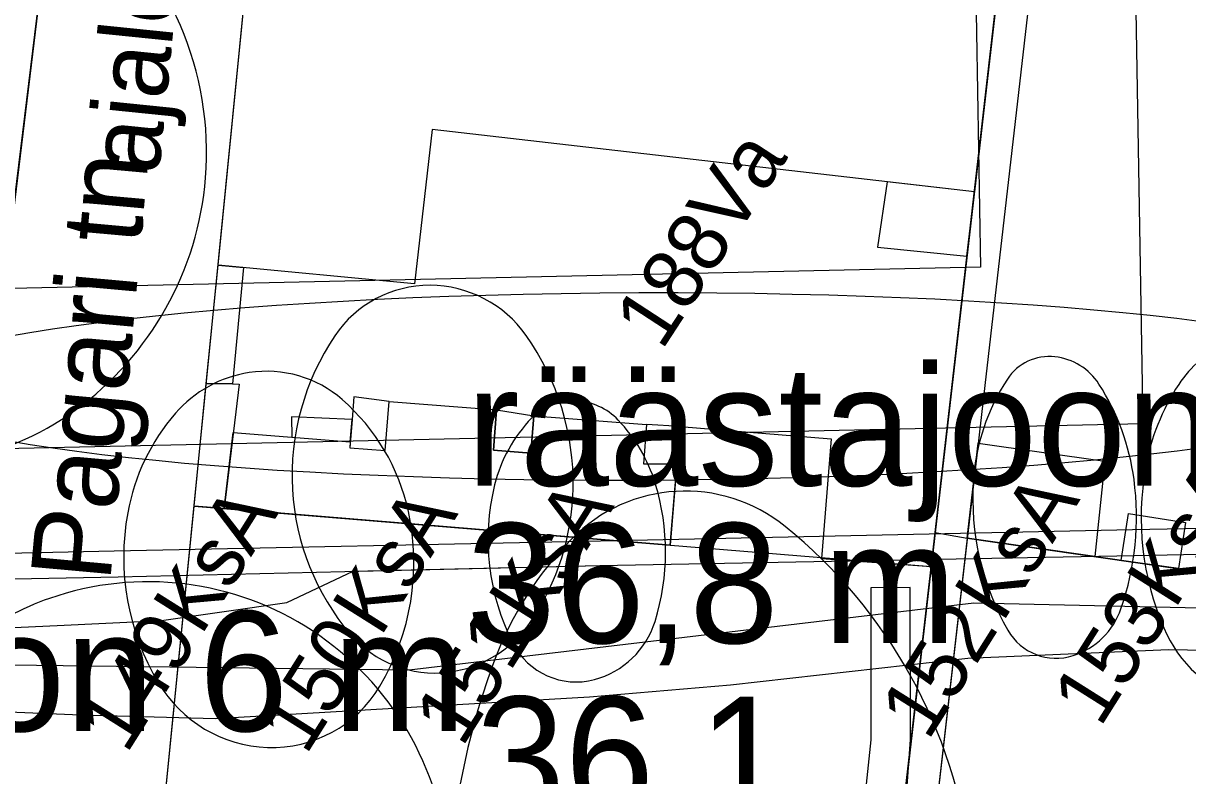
# Model space of a CAD drawing. Extents: x 738423 to 738903, y 6589762 to 6590172.
# Drawn here: x 738632.2 to 738661.32, y 6589875.49 to 6589894.31 of the extents above; entities that cross this region are included whole.
import ezdxf

# ---------------------------------------------------------------- set-up
doc = ezdxf.new("R2010")
doc.units = 0
for name, color, linetype in [('_1927_hoonestus', 7, 'Continuous'), ('_1927_katuse_kalded', 7, 'Continuous'), ('_1927_koordin_punktid_nr', 7, 'Continuous'), ('_1927_krundi_piir', 7, 'Continuous'), ('_a_ajalooline_maapind', 7, 'Continuous'), ('_a_olol_maapind', 7, 'Continuous'), ('_arheol_Raamatukogu_tranžee', 7, 'Continuous'), ('a_dendro_II_Vkl_puu', 7, 'Continuous'), ('a_dendro_III_vk_puu', 7, 'Continuous'), ('a_dendro_puu_nr', 7, 'Continuous'), ('a_dendro_V_vk_puu', 7, 'Continuous'), ('Default', 7, 'Continuous'), ('v_dp_jalak_liikumine', 7, 'Continuous'), ('v_olol_kitsendus_tehnov', 7, 'Continuous'), ('v_olol_kivimuur', 7, 'Continuous'), ('v_olol_transp_jjt_jalg', 7, 'Continuous'), ('v_vormistus_tekst', 7, 'Continuous')]:
    doc.layers.add(name, color=color, linetype=linetype)

# ---------------------------------------------------------------- blocks, each defined once
blk = doc.blocks.new('_U577')
at = {"layer": 'Default'}
for centre, radius, start, end in [((0.0003539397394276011, -0.0024772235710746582), 0.01753301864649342, 95.06339460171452, 143.64928581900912), ((0.0003509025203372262, -0.0024429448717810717), 0.017498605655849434, 47.6139328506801, 95.06339460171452), ((0.006587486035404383, 0.004390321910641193), 0.008247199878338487, 335.85757945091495, 47.613932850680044), ((-0.007106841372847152, 0.0030134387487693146), 0.008269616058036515, 143.6492858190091, 217.25092224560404), ((0.00326511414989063, 0.0058794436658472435), 0.011888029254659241, 301.16151048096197, 335.85757945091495), ((-0.004085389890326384, 0.00531108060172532), 0.012065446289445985, 217.2509222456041, 249.96613917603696), ((-0.0012283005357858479, 0.013310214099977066), 0.02057175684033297, 274.9595126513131, 301.16151048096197), ((-0.0012168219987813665, 0.01317793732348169), 0.020438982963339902, 249.96613917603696, 274.9595126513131)]:
    blk.add_arc(centre, radius, start, end, dxfattribs=at)
blk = doc.blocks.new('_U581')
at = {"layer": 'Default'}
for centre, radius, start, end in [((-0.0003533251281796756, -0.035605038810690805), 0.04161816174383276, 90.22599422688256, 110.7235512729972), ((-0.0003746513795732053, -0.03019827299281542), 0.0362113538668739, 73.7512051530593, 90.22599422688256), ((0.004875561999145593, -0.012184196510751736), 0.01744778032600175, 49.92756766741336, 73.75120515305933), ((-0.007667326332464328, -0.016273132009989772), 0.02094892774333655, 110.7235512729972, 139.77080809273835), ((0.010993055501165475, -0.004912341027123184), 0.007944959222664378, 325.34619088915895, 49.92756766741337), ((-0.017226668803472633, -0.008186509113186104), 0.00842796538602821, 139.77080809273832, 235.64822831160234), ((-0.003462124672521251, 0.005079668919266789), 0.025517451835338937, 281.2397286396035, 325.3461908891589), ((-0.004520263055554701, 0.010404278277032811), 0.030946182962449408, 235.64822831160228, 281.2397286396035)]:
    blk.add_arc(centre, radius, start, end, dxfattribs=at)
blk = doc.blocks.new('_U582')
at = {"layer": 'Default'}
for centre, radius, start, end in [((-0.0007850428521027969, -0.005273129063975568), 0.015274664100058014, 90.12335565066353, 129.24551704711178), ((-0.000785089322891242, -0.005251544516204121), 0.015253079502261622, 56.96948488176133, 90.12335565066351), ((-0.0006696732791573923, -0.005074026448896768), 0.015041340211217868, 23.57628563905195, 56.969484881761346), ((-0.0009275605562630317, -0.005098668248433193), 0.0150493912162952, 129.24551704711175, 168.67143080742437), ((-0.0005917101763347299, -0.0050400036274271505), 0.014956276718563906, 330.9480012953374, 23.57628563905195), ((-0.0010119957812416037, -0.005081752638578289), 0.014963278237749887, 168.6714308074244, 224.00059475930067), ((-0.0008142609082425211, -0.004916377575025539), 0.015210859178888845, 278.7954697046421, 330.9480012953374), ((-0.0008177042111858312, -0.0048941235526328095), 0.01523337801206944, 224.00059475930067, 278.7954697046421)]:
    blk.add_arc(centre, radius, start, end, dxfattribs=at)
blk = doc.blocks.new('_U599')
at = {"layer": 'Default'}
for centre, radius, start, end in [((-0.0018151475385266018, -0.00620660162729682), 0.012288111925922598, 83.93806732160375, 125.09681026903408), ((-0.0016240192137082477, -0.0044068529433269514), 0.010478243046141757, 53.38644184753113, 83.93806732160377), ((-0.005065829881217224, -0.0015808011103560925), 0.006634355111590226, 125.09681026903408, 182.2562888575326), ((0.0009823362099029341, -0.0008991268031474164), 0.006108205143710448, 13.013863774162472, 53.386441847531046), ((0.0013255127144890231, -0.0008198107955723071), 0.005755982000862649, 323.219360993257, 13.013863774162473), ((-0.005418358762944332, -0.0015946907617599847), 0.006281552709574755, 182.25628885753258, 243.4810712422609), ((-0.0023411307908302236, 0.0019212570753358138), 0.010333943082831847, 286.5947773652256, 323.21936099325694), ((-0.002835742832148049, 0.0035809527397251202), 0.012065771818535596, 243.48107124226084, 286.5947773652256)]:
    blk.add_arc(centre, radius, start, end, dxfattribs=at)
blk = doc.blocks.new('_U600')
at = {"layer": 'Default'}
for centre, radius, start, end in [((0.0009964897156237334, -0.005254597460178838), 0.012167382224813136, 97.43302717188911, 134.77200971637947), ((0.0010458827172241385, -0.005633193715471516), 0.012549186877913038, 60.34283130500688, 97.43302717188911), ((0.004430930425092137, 0.0003117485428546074), 0.005708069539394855, 4.068377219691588, 60.342831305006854), ((-0.00366957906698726, -0.0005512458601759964), 0.005542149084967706, 134.77200971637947, 191.4000956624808), ((0.004221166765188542, 0.00029682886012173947), 0.005918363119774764, 309.53088612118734, 4.068377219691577), ((-0.0033526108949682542, -0.00048733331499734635), 0.005865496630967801, 191.4000956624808, 240.15642242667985), ((-0.0001874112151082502, 0.005638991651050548), 0.012844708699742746, 273.2918787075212, 309.53088612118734), ((-0.00015555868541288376, 0.005085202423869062), 0.01229000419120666, 240.1564224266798, 273.2918787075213)]:
    blk.add_arc(centre, radius, start, end, dxfattribs=at)
blk = doc.blocks.new('_U601')
at = {"layer": 'Default'}
for centre, radius, start, end in [((-0.0022618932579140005, -0.007197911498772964), 0.011375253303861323, 80.41226363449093, 121.45839542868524), ((-0.0015900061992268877, -0.0032202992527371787), 0.007341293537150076, 50.23157485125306, 80.41226363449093), ((-0.006343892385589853, -0.000525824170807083), 0.0035535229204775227, 121.45839542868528, 199.15406508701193), ((0.0012669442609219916, 0.00021256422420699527), 0.0028751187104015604, 1.0658769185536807, 50.231574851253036), ((0.0009900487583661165, 0.00020741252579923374), 0.003152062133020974, 318.0268318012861, 1.065876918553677), ((-0.0055983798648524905, -0.00026687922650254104), 0.0043427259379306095, 199.15406508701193, 257.05060838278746), ((-0.002592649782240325, 0.0034302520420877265), 0.007971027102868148, 291.35378822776, 318.02683180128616), ((-0.003949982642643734, 0.006901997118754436), 0.011698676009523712, 257.05060838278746, 291.35378822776)]:
    blk.add_arc(centre, radius, start, end, dxfattribs=at)
blk = doc.blocks.new('_U602')
at = {"layer": 'Default'}
for centre, radius, start, end in [((-0.0002190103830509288, -0.009310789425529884), 0.013330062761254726, 90.637213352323, 124.05772412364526), ((-0.00025028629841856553, -0.0064986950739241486), 0.010517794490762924, 61.017455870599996, 90.63721335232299), ((0.00363187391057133, 0.000509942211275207), 0.002505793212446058, 357.8576766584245, 61.01745587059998), ((-0.006126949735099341, -0.000570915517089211), 0.0027806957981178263, 124.05772412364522, 202.09056835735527), ((0.0031090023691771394, 0.0005295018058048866), 0.0030290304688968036, 307.12239889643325, 357.8576766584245), ((-0.005235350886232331, -0.00020904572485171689), 0.0037429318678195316, 202.09056835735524, 255.22684119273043), ((-0.0020794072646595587, 0.007384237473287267), 0.011625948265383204, 281.859178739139, 307.1223988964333), ((-0.0025907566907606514, 0.00981936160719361), 0.014114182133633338, 255.22684119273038, 281.859178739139)]:
    blk.add_arc(centre, radius, start, end, dxfattribs=at)
blk = doc.blocks.new('_U603')
at = {"layer": 'Default'}
for centre, radius, start, end in [((-0.0017965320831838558, -0.010040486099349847), 0.014131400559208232, 84.19507760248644, 117.35483362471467), ((-0.0014956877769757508, -0.007081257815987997), 0.01115691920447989, 61.01745587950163, 84.19507760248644), ((-0.005240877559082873, -0.003382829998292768), 0.0066355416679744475, 117.35483362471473, 166.57279405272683), ((0.0012008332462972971, -0.0022131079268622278), 0.005591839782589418, 28.048391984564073, 61.017455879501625), ((0.0023609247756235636, -0.0015950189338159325), 0.0042773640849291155, 326.65781354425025, 28.048391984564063), ((-0.007049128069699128, -0.002951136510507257), 0.004776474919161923, 166.57279405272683, 243.48107124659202), ((-0.002429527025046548, 0.001556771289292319), 0.010011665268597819, 287.6753935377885, 326.6578135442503), ((-0.0033532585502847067, 0.004455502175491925), 0.0130540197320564, 243.48107124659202, 287.6753935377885)]:
    blk.add_arc(centre, radius, start, end, dxfattribs=at)
blk = doc.blocks.new('_U638')
at = {"layer": 'Default'}
for centre, radius, start, end in [((0.0017785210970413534, -0.00597414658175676), 0.01618526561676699, 99.23130900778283, 132.97828324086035), ((0.0017967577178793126, -0.006086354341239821), 0.016298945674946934, 62.43823725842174, 99.23130900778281), ((0.002383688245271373, -0.0049618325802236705), 0.015030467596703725, 24.06586474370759, 62.43823725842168), ((0.0009222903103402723, -0.005055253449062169), 0.014929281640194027, 132.97828324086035, 168.16056229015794), ((0.0028454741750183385, -0.004755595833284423), 0.014524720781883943, 325.34619089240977, 24.065864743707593), ((0.00048369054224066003, -0.004963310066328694), 0.0144811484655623, 168.16056229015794, 220.24997545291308), ((0.0015713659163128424, -0.003874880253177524), 0.016073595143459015, 269.78694623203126, 325.3461908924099), ((0.0015707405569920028, -0.004043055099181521), 0.01590541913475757, 220.24997545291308, 269.78694623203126)]:
    blk.add_arc(centre, radius, start, end, dxfattribs=at)

msp = doc.modelspace()

# ---------------------------------------------------------------- linework, layer by layer
at = {"layer": '_1927_hoonestus'}
for points in [[(738598.7561479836, 6589884.064893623), (738598.7561479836, 6589884.064893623), (738600.1654182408, 6589891.510843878), (738617.1576277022, 6589889.916511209), (738616.9587005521, 6589887.781161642), (738616.9587005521, 6589887.781161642), (738621.4793553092, 6589887.4869466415), (738621.2187353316, 6589884.178665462), (738631.1763472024, 6589883.225550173), (738634.3211426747, 6589909.080822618), (738624.2071897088, 6589909.313105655), (738622.5673353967, 6589895.324185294), (738590.9372064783, 6589898.13516685), (738590.9372064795, 6589898.13516685), (738586.1827055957, 6589872.62061175), (738613.3249623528, 6589869.722398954), (738613.2710881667, 6589869.728151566), (738614.3523733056, 6589877.812429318), (738614.3523733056, 6589877.812429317), (738614.3523733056, 6589877.812429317), (738615.0233334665, 6589882.235576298)], [(738648.5572709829, 6589901.456803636), (738657.987576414, 6589900.425538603), (738653.971798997, 6589865.440014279), (738653.1607330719, 6589865.55689891), (738656.7595760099, 6589896.804037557), (738648.2717006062, 6589897.771571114)], [(738638.1290908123, 6589898.927727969), (738648.2717006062, 6589897.771571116), (738656.7595760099, 6589896.804037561), (738655.986351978, 6589890.090480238), (738642.4241395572, 6589891.652487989), (738641.9789662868, 6589887.787248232), (738637.0682383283, 6589888.257436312)], [(738653.8022581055, 6589890.342030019), (738653.5619854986, 6589888.708327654), (738655.8016860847, 6589888.487109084), (738655.9863519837, 6589890.090480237)], [(738637.0682383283, 6589888.257436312), (738637.7063996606, 6589888.196334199), (738637.4278377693, 6589885.286984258), (738636.7738590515, 6589885.296503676)], [(738636.7738590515, 6589885.296503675), (738637.4278377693, 6589885.286984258), (738637.5955099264, 6589885.284543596), (738637.2234706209, 6589882.1717191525), (738636.4693724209, 6589882.233909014)], [(738640.4634358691, 6589884.9659766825), (738640.4201156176, 6589884.398018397), (738640.3646553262, 6589883.692063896), (738641.2492312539, 6589883.6225709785), (738641.3454367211, 6589884.847171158)], [(738637.4504146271, 6589884.070542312), (738640.3763307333, 6589883.840680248), (738640.3646553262, 6589883.692063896), (738641.2492312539, 6589883.6225709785), (738641.3454367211, 6589884.847171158), (738644.036789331, 6589884.63573657), (738643.9578925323, 6589883.631458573), (738644.8937721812, 6589883.557935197), (738644.9672955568, 6589884.4938148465), (738647.7878451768, 6589884.272230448), (738647.7104346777, 6589883.286871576), (738648.5480034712, 6589883.287381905), (738648.3801174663, 6589881.2516396), (738637.2234706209, 6589882.1717191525)], [(738638.9095096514, 6589884.461267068), (738638.9133726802, 6589883.955611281), (738640.3763307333, 6589883.840680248), (738640.4201156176, 6589884.398018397)], [(738644.036789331, 6589884.63573657), (738644.9672955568, 6589884.4938148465), (738644.8937721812, 6589883.557935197), (738643.9578925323, 6589883.631458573)], [(738635.0048101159, 6589867.503013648), (738636.4693724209, 6589882.233909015), (738648.3801174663, 6589881.2516396), (738648.6253999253, 6589884.225871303), (738652.4080567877, 6589883.913918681), (738652.1613927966, 6589880.922934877), (738654.9075674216, 6589880.723877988), (738653.1607330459, 6589865.556898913)], [(738647.7878451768, 6589884.272230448), (738647.7104346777, 6589883.286871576), (738648.5480034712, 6589883.287381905), (738648.6253999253, 6589884.225871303)], [(738656.0797019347, 6589883.804102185), (738659.2472265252, 6589883.359307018), (738659.0011896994, 6589880.969469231), (738655.8073303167, 6589881.431195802)], [(738659.657029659, 6589880.874656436), (738659.8440383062, 6589882.050860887), (738661.2675031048, 6589881.8245394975), (738661.0902654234, 6589880.667457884)], [(738686.9079452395, 6589860.693508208), (738690.3471033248, 6589876.437885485), (738655.8073303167, 6589881.431195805), (738653.971798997, 6589865.440014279)]]:
    msp.add_lwpolyline(points, close=True, dxfattribs=at)
at = {"layer": '_1927_katuse_kalded'}
for points in [[(738634.3211545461, 6589909.080822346), (738627.9783805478, 6589903.577252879), (738626.1975412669, 6589883.702107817), (738631.1763472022, 6589883.225550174)], [(738635.7370912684, 6589874.86846133), (738636.469372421, 6589882.233909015), (738654.9075674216, 6589880.723877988), (738654.051851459, 6589873.294080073)], [(738654.1081769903, 6589873.783129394), (738655.0056644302, 6589881.575610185), (738655.8073303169, 6589881.431195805), (738690.3471033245, 6589876.437885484), (738688.7887442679, 6589869.303757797)]]:
    msp.add_lwpolyline(points, close=True, dxfattribs=at)
at = {"layer": '_1927_krundi_piir'}
msp.add_line((738656.7595760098, 6589896.804037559), (738653.160733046, 6589865.556898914), dxfattribs=at)
for points in [[(738638.2396178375, 6589940.94571321), (738636.5091918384, 6589926.8911045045), (738634.3211426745, 6589909.080822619), (738629.2817413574, 6589868.018556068)], [(738699.2597677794, 6589917.23983417), (738686.9079452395, 6589860.693508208), (738653.160733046, 6589865.556898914), (738635.0048101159, 6589867.503013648), (738638.1290908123, 6589898.927727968), (738639.279366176, 6589910.5516114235)]]:
    msp.add_lwpolyline(points, dxfattribs=at)
at = {"layer": '_arheol_Raamatukogu_tranžee'}
msp.add_lwpolyline([(738654.380448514, 6589880.19889457), (738653.399682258, 6589880.189044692), (738653.399682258, 6589876.385332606), (738653.2151971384, 6589874.643537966), (738652.8999019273, 6589873.047297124), (738652.8999019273, 6589864.483676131), (738651.0999019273, 6589864.483676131), (738651.0999019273, 6589848.68367613), (738652.0999019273, 6589848.68367613), (738652.0999019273, 6589860.18367613), (738653.9088242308, 6589860.18367613), (738653.9088242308, 6589871.007189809), (738653.923828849, 6589873.109334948), (738654.2799277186, 6589874.894069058), (738654.3869752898, 6589876.385332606), (738654.380448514, 6589880.19889457)], dxfattribs=at)
at = {"layer": 'a_dendro_V_vk_puu'}
msp.add_ellipse((738647.6051953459, 6589885.222999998), major_axis=(19.017612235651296, 0.06685041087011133), ratio=0.12347597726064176, dxfattribs=at)
at = {"layer": 'v_dp_jalak_liikumine'}
msp.add_lwpolyline([(738581.4723412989, 6589878.120522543), (738587.4015406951, 6589878.120522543), (738606.5184403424, 6589878.608756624), (738618.5434188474, 6589878.425595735), (738641.8496480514, 6589878.136204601), (738655.9728153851, 6589879.813491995), (738670.3230528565, 6589879.497843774), (738680.5529887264, 6589878.338003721), (738697.9581193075, 6589880.397873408), (738705.6932562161, 6589881.082962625), (738725.5888177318, 6589880.833839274), (738742.0007790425, 6589880.833839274), (738745.4047050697, 6589880.7783847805), (738754.5304628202, 6589882.343075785), (738758.8441211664, 6589885.746853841)], dxfattribs=at)
at = {"layer": 'v_olol_kitsendus_tehnov'}
msp.add_lwpolyline([(738586.6888850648, 6589865.143953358), (738591.9451522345, 6589864.37135473), (738592.5597488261, 6589882.810896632), (738660.2059563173, 6589884.29620018), (738660.0179515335, 6589895.618846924), (738656.018502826, 6589895.552438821), (738656.1404538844, 6589888.2078982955), (738592.1413769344, 6589886.802674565), (738592.1718913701, 6589887.668806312), (738591.66193984, 6589894.040728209), (738588.6389999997, 6589893.962)], dxfattribs=at)
at = {"layer": 'v_olol_kivimuur'}
msp.add_lwpolyline([(738666.875, 6589881.770000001), (738659.944, 6589881.638000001), (738646.635, 6589881.357999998), (738634.471, 6589881.1039999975), (738616.7840000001, 6589880.725), (738614.0280000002, 6589880.692999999), (738614.0280000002, 6589880.692999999), (738614.051, 6589880.119999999), (738616.8040000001, 6589880.117999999), (738634.566, 6589880.464999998), (738646.6210000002, 6589880.749999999), (738659.9889999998, 6589880.999), (738668.9849999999, 6589881.181999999)], dxfattribs=at)
at = {"layer": 'v_olol_transp_jjt_jalg'}
for points in [[(738628.9060000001, 6589879.058000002), (738633.0459999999, 6589879.249), (738635.6520000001, 6589879.367999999), (738638.788, 6589879.821999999), (738640.446620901, 6589880.604027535), (738646.6210000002, 6589880.749999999), (738659.9889999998, 6589880.999), (738668.9849999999, 6589881.181999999)], [(738662.7329999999, 6589878.602000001), (738660.8409999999, 6589878.633999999), (738655.8229999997, 6589878.420000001), (738649.8879999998, 6589877.751000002), (738646.3560000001, 6589877.454000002), (738637.002, 6589876.907999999), (738633.6249999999, 6589877.004), (738621.881, 6589877.496000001)]]:
    msp.add_lwpolyline(points, dxfattribs=at)

# ---------------------------------------------------------------- block references
at = {"layer": 'a_dendro_II_Vkl_puu', "xscale": 500.0000000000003, "yscale": 500.0000000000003, "rotation": 85.69234851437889}
msp.add_blockref('_U577', (738668.8083105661, 6589871.8624428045), dxfattribs=at)
at = {"layer": 'a_dendro_III_vk_puu', "xscale": 500.0000000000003, "yscale": 500.0000000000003, "rotation": 85.69234851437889}
for name, p in [('_U638', (738626.7529999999, 6589890.438999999)), ('_U600', (738642.3469999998, 6589882.678999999)), ('_U603', (738662.2849999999, 6589883.225000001)), ('_U599', (738637.8254716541, 6589882.095904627)), ('_U602', (738657.9769999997, 6589882.892000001)), ('_U601', (738646.0029999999, 6589882.794)), ('_U581', (738645.893310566, 6589873.338442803)), ('_U582', (738632.829310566, 6589873.347442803))]:
    msp.add_blockref(name, p, dxfattribs=at)

# ---------------------------------------------------------------- texts
at = {"layer": '_1927_koordin_punktid_nr'}
msp.add_text('Pagari tn', height=1.9999999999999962, rotation=84.83058672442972, dxfattribs=at).set_placement((738634.3685444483, 6589880.313885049))
at = {"layer": '_a_ajalooline_maapind'}
msp.add_text('36,1', height=3, dxfattribs=at).set_placement((738643.5130339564, 6589874.467036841))
at = {"layer": '_a_olol_maapind'}
for s, p in [('räästajoon 9 m', (738643.2807664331, 6589882.74118056)), ('36,8 m', (738643.2807664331, 6589878.804707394)), ('räästajoon 6 m', (738616.742311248, 6589876.603607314))]:
    msp.add_text(s, height=3, dxfattribs=at).set_placement(p)
at = {"layer": 'a_dendro_puu_nr'}
for s, height, rotation, p in [('188Va', 1.5000000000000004, 56.88665020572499, (738648.1657866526, 6589886.1009146)), ('KsA', 1.5000000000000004, 57.784522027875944, (738660.9950811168, 6589879.626746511)), ('KsA', 1.5000000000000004, 57.784522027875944, (738656.6870811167, 6589879.293746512)), ('KsA', 1.4999999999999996, 57.784522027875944, (738636.6414951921, 6589878.966023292)), ('KsA', 1.4999999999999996, 57.784522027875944, (738641.1291119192, 6589878.934850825)), ('KsA', 1.5000000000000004, 57.784522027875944, (738645.035532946, 6589879.1294167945)), ('153', 1.5000000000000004, 57.784522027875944, (738659.1312141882, 6589876.668748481)), ('152', 1.5000000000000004, 57.784522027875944, (738654.8232141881, 6589876.335748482)), ('9', 1.4999999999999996, 57.784522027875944, (738636.020206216, 6589877.9800239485)), ('151', 1.5000000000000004, 57.784522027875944, (738643.1716660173, 6589876.171418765)), ('150', 1.4999999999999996, 57.784522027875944, (738639.2652449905, 6589875.976852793)), ('4', 1.4999999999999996, 57.784522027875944, (738635.3989172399, 6589876.9940246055)), ('1', 1.4999999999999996, 57.784522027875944, (738634.7776282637, 6589876.008025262))]:
    msp.add_text(s, height=height, rotation=rotation, dxfattribs=at).set_placement(p)
at = {"layer": 'v_vormistus_tekst'}
msp.add_text('ajalooline Pagari tänav', height=1.7999999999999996, rotation=84.19514024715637, dxfattribs=at).set_placement((738635.5819194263, 6589890.509699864))

doc.saveas('drawing.dxf')
